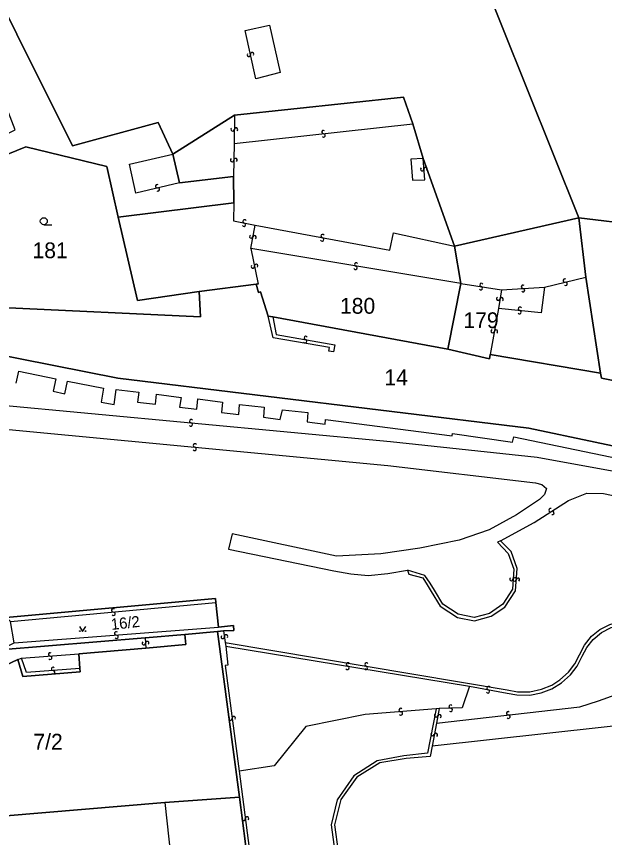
# Model space of a CAD drawing. Extents: x -600309 to -598967, y -1161267 to -1160292.
# Drawn here: x -599203 to -599139.6, y -1160958.3 to -1160869.9 of the extents above; entities that cross this region are included whole.
import ezdxf

# ---------------------------------------------------------------- set-up
doc = ezdxf.new("R2010")
doc.units = 0
for name, color, linetype in [('Level 1', 7, 'Continuous'), ('Level 13', 7, 'Continuous'), ('Level 3', 7, 'Continuous'), ('Level 4', 7, 'Continuous'), ('Level 5', 7, 'Continuous'), ('Level 60', 7, 'Continuous')]:
    doc.layers.add(name, color=color, linetype=linetype)

msp = doc.modelspace()

# ---------------------------------------------------------------- linework, layer by layer
at = {"layer": 'Level 1'}
for points in [[(-599186.14, -1160884.73), (-599187.69, -1160881.34), (-599196.93, -1160883.84), (-599214.95, -1160847.74), (-599222.56, -1160818.46), (-599226.63, -1160790.42), (-599226.46, -1160779.61), (-599224.76, -1160776.46), (-599213.89, -1160771.2), (-599202.26, -1160766.2), (-599191.88, -1160764.74), (-599191.33, -1160772.76), (-599189.43, -1160772.06)], [(-599142.41, -1160891.59), (-599164.5, -1160836.42)], [(-599179.49, -1160880.56), (-599161.27, -1160878.6), (-599160.28, -1160881.49)], [(-599186.14, -1160884.73), (-599179.49, -1160880.56)], [(-599160.28, -1160881.49), (-599159.17, -1160885.23)], [(-599210.91, -1160887.57), (-599201.97, -1160883.95), (-599193.25, -1160886.06), (-599192, -1160891.53)], [(-599185.42, -1160887.84), (-599186.14, -1160884.73)], [(-599159.17, -1160885.23), (-599155.79, -1160894.66)], [(-599179.59, -1160887.16), (-599185.42, -1160887.84)], [(-599179.57, -1160890), (-599179.59, -1160887.16)], [(-599192, -1160891.53), (-599179.57, -1160890)], [(-599183.27, -1160899.54), (-599189.93, -1160900.51), (-599192, -1160891.53)], [(-599155.79, -1160894.66), (-599142.41, -1160891.59)], [(-599135.82, -1160892.38), (-599142.41, -1160891.59)], [(-599141.64, -1160898), (-599142.41, -1160891.59)], [(-599155.1, -1160898.67), (-599155.79, -1160894.66)], [(-599140.05, -1160908.33), (-599141.64, -1160898)], [(-599177.14, -1160898.74), (-599183.27, -1160899.54)], [(-599175.86, -1160902.19), (-599176.67, -1160899.57), (-599176.9, -1160899.65), (-599177.14, -1160898.74)], [(-599156.5, -1160905.76), (-599155.1, -1160898.67)], [(-599183.27, -1160899.54), (-599183.16, -1160902.27), (-599204.59, -1160901.25), (-599205.47, -1160899.62)], [(-599175.37, -1160902.28), (-599175.86, -1160902.19)], [(-599156.5, -1160905.76), (-599175.37, -1160902.28)], [(-599090.81, -1160941.28), (-599095.27, -1160935.88), (-599099.26, -1160932.22), (-599109.1, -1160924.77), (-599133.51, -1160917.28), (-599147.77, -1160914.25), (-599192.06, -1160908.87), (-599213.12, -1160904.7), (-599222.87, -1160911.11), (-599239.81, -1160919.79)], [(-599151.93, -1160906.31), (-599152.02, -1160906.79), (-599156.5, -1160905.76)], [(-599140.05, -1160908.33), (-599151.93, -1160906.31)], [(-599134.1, -1160910.05), (-599139.96, -1160908.88), (-599140.05, -1160908.33)], [(-599204.06, -1160934.65), (-599181.54, -1160932.59), (-599181.49, -1160933.03)], [(-599181.49, -1160933.03), (-599181.2, -1160935.69)], [(-599181.2, -1160935.69), (-599179.58, -1160935.49), (-599179.54, -1160936.05), (-599180.68, -1160936.08)], [(-599204.74, -1160938.11), (-599189.1, -1160936.84)], [(-599189.1, -1160936.84), (-599184.83, -1160936.46)], [(-599189.04, -1160937.95), (-599184.71, -1160937.54), (-599184.83, -1160936.46)], [(-599184.83, -1160936.46), (-599181.3, -1160936.16)], [(-599180.68, -1160936.08), (-599181.3, -1160936.16)], [(-599181.3, -1160936.16), (-599178.93, -1160953.98)], [(-599196.26, -1160938.56), (-599189.04, -1160937.95)], [(-599196.15, -1160940.15), (-599196.26, -1160938.56)], [(-599228.74, -1160948.86), (-599220.85, -1160947.69), (-599202.82, -1160939.17)], [(-599202.82, -1160939.17), (-599202.27, -1160941.01), (-599196.12, -1160940.49), (-599196.15, -1160940.15)], [(-599225.89, -1160957.84), (-599186.97, -1160954.57)], [(-599186.97, -1160954.57), (-599178.93, -1160953.98)], [(-599178.93, -1160953.98), (-599177.98, -1160961.52), (-599177.34, -1160964.13), (-599176.24, -1160966.62), (-599174.52, -1160969.21), (-599172.33, -1160971.47), (-599158.73, -1160982.53), (-599145.9, -1160990.81), (-599145.8, -1160995.78)]]:
    msp.add_lwpolyline(points, dxfattribs=at)
at = {"layer": 'Level 13'}
for centre, start, end in [((-599177.941, -1160874.058), 139.63293, 11.73093), ((-599177.58, -1160873.982), 319.41848, 192.00848), ((-599179.684, -1160882.078), 126.78257, 359.37257), ((-599179.316, -1160882.083), 306.99703, 179.09503), ((-599169.919, -1160882.366), 43.66387, 275.76186), ((-599169.881, -1160882.733), 223.44941, 96.03941), ((-599179.734, -1160885.375), 125.86733, 358.45733), ((-599179.366, -1160885.386), 306.08178, 178.17978), ((-599159.264, -1160886.372), 131.65561, 3.75361), ((-599158.896, -1160886.347), 311.44116, 184.03116), ((-599187.811, -1160888.201), 50.2152, 282.8052), ((-599187.73, -1160888.56), 230.42966, 102.52766), ((-599178.39, -1160891.98), 25.44674, 257.54474), ((-599178.469, -1160892.34), 205.23229, 77.82229), ((-599177.681, -1160893.625), 116.808, 348.906), ((-599177.319, -1160893.695), 296.59354, 169.18354), ((-599169.985, -1160893.559), 26.94631, 259.04431), ((-599170.054, -1160893.921), 206.73186, 79.32186), ((-599177.52, -1160896.857), 139.16057, 11.75057), ((-599177.159, -1160896.783), 319.37503, 191.47303), ((-599166.452, -1160896.982), 207.96788, 80.06587), ((-599166.389, -1160896.619), 27.75342, 260.34342), ((-599152.89, -1160898.828), 28.52808, 260.62607), ((-599148.419, -1160899.026), 40.82605, 272.92405), ((-599143.901, -1160898.36), 50.89281, 282.99081), ((-599143.818, -1160898.719), 230.67836, 103.26836), ((-599152.949, -1160899.192), 208.31362, 80.90362), ((-599148.4, -1160899.394), 220.61159, 93.20159), ((-599151.081, -1160900.319), 117.78889, 350.37889), ((-599150.718, -1160900.382), 298.00335, 170.10134), ((-599148.74, -1160901.407), 31.21398, 263.80398), ((-599148.781, -1160901.773), 211.42843, 83.52643), ((-599151.681, -1160903.797), 117.20962, 349.79962), ((-599151.319, -1160903.864), 297.42407, 169.52207), ((-599171.873, -1160904.901), 207.00533, 79.59533), ((-599171.806, -1160904.539), 27.21978, 259.31778), ((-599184.188, -1160913.863), 211.79089, 84.38089), ((-599184.151, -1160913.497), 32.00535, 264.10335), ((-599183.778, -1160916.483), 211.70559, 84.29559), ((-599183.741, -1160916.117), 31.92005, 264.01805), ((-599145.449, -1160923.074), 70.23301, 302.33101), ((-599145.251, -1160923.385), 250.01855, 122.60855), ((-599149.664, -1160930.516), 123.18578, 355.77578), ((-599149.324, -1160930.545), 123.33781, 355.4358), ((-599149.296, -1160930.544), 303.40024, 175.49823), ((-599148.956, -1160930.574), 303.12335, 175.71335), ((-599192.555, -1160933.876), 42.67233, 274.77033), ((-599192.524, -1160934.243), 222.45788, 95.04788), ((-599192.222, -1160936.356), 41.76149, 273.85949), ((-599192.197, -1160936.724), 221.54703, 94.13703), ((-599180.752, -1160936.73), 136.69491, 9.28491), ((-599180.388, -1160936.671), 316.90937, 189.00737), ((-599189.254, -1160937.409), 130.25234, 2.84234), ((-599188.886, -1160937.392), 310.46679, 182.56479), ((-599199.353, -1160938.616), 41.82114, 273.91914), ((-599199.327, -1160938.984), 221.60669, 94.19669), ((-599167.258, -1160939.708), 28.02376, 260.12175), ((-599165.268, -1160939.698), 27.83081, 259.92881), ((-599199.033, -1160940.176), 41.34319, 273.93319), ((-599199.008, -1160940.544), 221.55765, 93.65565), ((-599167.321, -1160940.071), 207.8093, 80.3993), ((-599165.331, -1160940.061), 207.61635, 80.20635), ((-599152.116, -1160942.239), 27.1303, 259.2283), ((-599152.184, -1160942.601), 206.91584, 79.50584), ((-599161.593, -1160944.606), 41.55698, 274.14698), ((-599161.568, -1160944.974), 221.77144, 93.86944), ((-599156.204, -1160944.236), 38.77507, 271.36507), ((-599156.196, -1160944.604), 218.98952, 91.08752), ((-599150.019, -1160944.957), 43.83501, 275.933), ((-599179.923, -1160945.523), 134.70353, 7.29353), ((-599179.557, -1160945.477), 314.91799, 187.01599), ((-599157.761, -1160945.206), 116.62735, 349.21735), ((-599157.399, -1160945.275), 296.84181, 168.9398), ((-599149.98, -1160945.323), 223.62055, 96.21055), ((-599158.151, -1160947.214), 116.16095, 348.75095), ((-599157.789, -1160947.287), 296.3754, 168.4734), ((-599178.503, -1160956.343), 134.61361, 7.20361), ((-599178.137, -1160956.298), 314.82806, 186.92606)]:
    msp.add_arc(centre, 0.184, start, end, dxfattribs=at)
at = {"layer": 'Level 3'}
for points in [[(-599178.33, -1160871.42), (-599175.71, -1160870.84), (-599174.55, -1160875.95), (-599177.2, -1160876.62), (-599178.33, -1160871.42)], [(-599179.49, -1160880.56), (-599179.51, -1160883.61)], [(-599179.51, -1160883.61), (-599160.28, -1160881.49)], [(-599179.51, -1160883.61), (-599179.59, -1160887.16)], [(-599185.42, -1160887.84), (-599190.12, -1160888.93), (-599190.79, -1160885.84), (-599186.14, -1160884.73)], [(-599159.17, -1160885.23), (-599160.48, -1160885.29), (-599160.32, -1160887.54), (-599159, -1160887.5), (-599159.17, -1160885.23)], [(-599179.57, -1160890), (-599179.59, -1160891.91), (-599177.27, -1160892.4)], [(-599177.74, -1160894.92), (-599177.27, -1160892.4)], [(-599177.27, -1160892.4), (-599162.76, -1160895.07), (-599162.34, -1160893.21), (-599155.79, -1160894.66)], [(-599155.1, -1160898.67), (-599177.74, -1160894.92)], [(-599177.74, -1160894.92), (-599176.93, -1160898.73), (-599177.14, -1160898.74)], [(-599146.09, -1160899.07), (-599141.64, -1160898)], [(-599155.1, -1160898.67), (-599150.73, -1160899.35)], [(-599146.09, -1160899.07), (-599146.45, -1160901.83), (-599151.06, -1160901.35)], [(-599150.73, -1160899.35), (-599151.06, -1160901.35)], [(-599150.73, -1160899.35), (-599146.09, -1160899.07)], [(-599151.06, -1160901.35), (-599151.93, -1160906.31)], [(-599175.37, -1160902.28), (-599174.99, -1160904.15), (-599168.68, -1160905.28), (-599168.83, -1160906.05), (-599169.31, -1160905.97), (-599169.26, -1160905.56), (-599175.3, -1160904.51), (-599175.86, -1160902.19)], [(-599202.98, -1160909.4), (-599202.71, -1160908.12), (-599198.71, -1160908.95), (-599199.01, -1160910.28), (-599197.77, -1160910.55), (-599197.47, -1160909.18), (-599193.58, -1160909.96), (-599193.83, -1160911.46), (-599192.44, -1160911.7), (-599192.21, -1160910.08), (-599189.77, -1160910.37), (-599189.94, -1160911.46), (-599187.98, -1160911.67), (-599187.89, -1160910.61), (-599185.22, -1160910.94), (-599185.4, -1160912.01), (-599183.55, -1160912.2), (-599183.42, -1160911.11), (-599180.76, -1160911.45), (-599180.9, -1160912.58), (-599179.02, -1160912.79), (-599178.95, -1160911.69), (-599176.28, -1160912.01), (-599176.37, -1160913.06), (-599174.56, -1160913.32), (-599174.33, -1160912.29), (-599171.57, -1160912.58), (-599171.65, -1160913.59), (-599169.72, -1160913.81), (-599169.67, -1160913.31), (-599156.04, -1160915.08), (-599156.01, -1160914.83), (-599149.53, -1160915.76), (-599149.41, -1160915.17), (-599134.18, -1160918.35)], [(-599237.16, -1160924.23), (-599217.67, -1160913.88), (-599211.9, -1160912.1), (-599205.67, -1160911.66), (-599162.67, -1160915.7), (-599146.88, -1160917.38), (-599132.9, -1160919.94), (-599119.14, -1160923.19), (-599114.23, -1160925.05), (-599109.69, -1160927.43), (-599105.45, -1160930.09), (-599102.83, -1160932.05), (-599099.44, -1160935.38), (-599096.48, -1160939.5), (-599095.29, -1160943.46), (-599096.44, -1160948), (-599103.45, -1160958.99), (-599112.91, -1160969.26)], [(-599236.27, -1160926.87), (-599217.62, -1160916.69), (-599211.29, -1160914.58), (-599204.55, -1160914.31), (-599162.96, -1160918.28), (-599147.06, -1160920.15), (-599146.37, -1160920.32), (-599145.88, -1160920.74), (-599146.11, -1160921.4), (-599146.64, -1160921.92), (-599149.11, -1160923.59), (-599152.05, -1160925.2), (-599155.27, -1160926.31), (-599159.53, -1160927.18), (-599163.73, -1160927.77), (-599168.48, -1160928.03), (-599179.74, -1160925.62), (-599180.14, -1160927.28), (-599168.8, -1160929.61), (-599166.95, -1160929.93), (-599165.1, -1160930.12), (-599162.97, -1160929.91), (-599160.84, -1160929.55)], [(-599150.84, -1160926.37), (-599147.2, -1160924.43), (-599143.5, -1160922.04), (-599141.53, -1160921.24), (-599139.75, -1160921.28), (-599136.47, -1160921.97)], [(-599150.84, -1160926.37), (-599151.14, -1160926.53), (-599150, -1160927.74), (-599149.4, -1160929.45), (-599149.55, -1160931.61), (-599150.58, -1160933.21), (-599152.02, -1160934.21), (-599153.68, -1160934.63), (-599155.4, -1160934.28), (-599157.04, -1160933.2), (-599157.95, -1160931.7), (-599158.41, -1160930.94), (-599158.98, -1160930.12), (-599160.84, -1160929.55)], [(-599160.84, -1160929.55), (-599160.72, -1160929.96), (-599159.19, -1160930.38), (-599158.74, -1160931.12), (-599158.31, -1160931.86), (-599157.32, -1160933.44), (-599155.47, -1160934.65), (-599153.63, -1160935.01), (-599151.83, -1160934.49), (-599150.35, -1160933.52), (-599149.22, -1160931.77), (-599149.05, -1160929.36), (-599149.69, -1160927.53), (-599150.84, -1160926.37)], [(-599203.59, -1160935.08), (-599181.49, -1160933.03)], [(-599180.47, -1160937.33), (-599150.13, -1160942.43), (-599148.99, -1160942.65), (-599147.68, -1160942.65), (-599146.41, -1160942.38), (-599145.31, -1160941.93), (-599144.44, -1160941.37), (-599143.52, -1160940.53), (-599142.83, -1160939.62), (-599142.32, -1160938.66), (-599141.8, -1160937.62), (-599141.03, -1160936.66), (-599140.13, -1160935.93), (-599139.07, -1160935.39), (-599137.87, -1160935.04), (-599136.58, -1160934.98)], [(-599203.22, -1160937.38), (-599181.2, -1160935.69)], [(-599154.17, -1160942.05), (-599150.13, -1160942.78), (-599149.06, -1160942.99), (-599147.67, -1160943.01), (-599146.46, -1160942.77), (-599145.32, -1160942.33), (-599144.25, -1160941.69), (-599143.3, -1160940.82), (-599142.58, -1160939.88), (-599142.02, -1160938.81), (-599141.54, -1160937.89), (-599140.84, -1160937), (-599139.94, -1160936.26), (-599138.93, -1160935.73), (-599137.7, -1160935.41), (-599136.58, -1160935.36)], [(-599189.1, -1160936.84), (-599189.04, -1160937.95)], [(-599180.68, -1160936.08), (-599180.47, -1160937.33)], [(-599180.41, -1160937.73), (-599180.2, -1160939.77), (-599180.5, -1160939.8), (-599178.99, -1160951.2)], [(-599180.47, -1160937.33), (-599180.41, -1160937.73)], [(-599180.41, -1160937.73), (-599154.17, -1160942.05)], [(-599202.43, -1160939.04), (-599196.26, -1160938.56)], [(-599157.73, -1160946.02), (-599142.28, -1160944.27), (-599140.29, -1160943.63), (-599138.37, -1160942.94), (-599137.4, -1160942.21), (-599136.78, -1160940.53), (-599136.47, -1160938.59)], [(-599202.82, -1160939.17), (-599202.43, -1160939.04)], [(-599196.15, -1160940.15), (-599201.89, -1160940.57), (-599202.43, -1160939.04)], [(-599154.17, -1160942.05), (-599154.96, -1160944.39), (-599157.44, -1160944.46)], [(-599157.75, -1160944.49), (-599165.42, -1160945.08), (-599171.8, -1160946.39), (-599175.2, -1160950.63), (-599178.99, -1160951.2)], [(-599157.75, -1160944.49), (-599158.69, -1160949.24), (-599161.23, -1160949.53), (-599164.13, -1160950.09), (-599166.62, -1160951.69), (-599168.44, -1160954.29), (-599169.07, -1160956.96), (-599168.68, -1160959.89), (-599166.9, -1160962.85), (-599169.94, -1160967.32), (-599173.79, -1160965.72), (-599175.85, -1160966.56)], [(-599167.37, -1160964.08), (-599145.71, -1160979.34), (-599143.04, -1160980.89), (-599139.54, -1160981.78), (-599136.05, -1160981.78), (-599132.77, -1160981.34), (-599129.15, -1160979.87), (-599126.44, -1160978.08), (-599119.63, -1160972.32), (-599112.51, -1160965.29), (-599105.65, -1160957.58), (-599100.74, -1160950.13), (-599100.79, -1160948.38), (-599101.42, -1160946.69), (-599102.51, -1160945.5), (-599103.95, -1160944.85), (-599105.64, -1160944.69), (-599120.09, -1160944.82), (-599133.48, -1160945.79), (-599158.21, -1160948.49)], [(-599157.44, -1160944.46), (-599157.75, -1160944.49)], [(-599157.44, -1160944.46), (-599157.73, -1160946.02)], [(-599157.73, -1160946.02), (-599158.21, -1160948.49)], [(-599158.21, -1160948.49), (-599158.42, -1160949.61), (-599160.98, -1160949.83), (-599163.83, -1160950.31), (-599166.3, -1160951.83), (-599168.04, -1160954.23), (-599168.72, -1160956.97), (-599168.32, -1160959.84), (-599166.49, -1160962.75), (-599167.37, -1160964.08)], [(-599178.99, -1160951.2), (-599177.65, -1160961.44), (-599177.01, -1160964.12), (-599175.85, -1160966.56)], [(-599186.97, -1160954.57), (-599185.91, -1160964.43)]]:
    msp.add_lwpolyline(points, dxfattribs=at)
at = {"layer": 'Level 5'}
msp.add_line((-599200.02, -1160892.34), (-599199.145, -1160892.34), dxfattribs=at)
msp.add_lwpolyline([(-599196.181, -1160935.63), (-599195.84, -1160936.14), (-599195.5, -1160935.63)], dxfattribs=at)
for centre, radius in [((-599200.02, -1160891.965), 0.375), ((-599196.146, -1160936.106), 0.034), ((-599195.535, -1160936.106), 0.034)]:
    msp.add_circle(centre, radius, dxfattribs=at)
at = {"layer": 'Level 60'}
for points in [[(-599189.43, -1160772.06), (-599179.89, -1160797.48), (-599173.47, -1160813.83), (-599164.5, -1160836.42), (-599142.41, -1160891.59), (-599155.79, -1160894.66), (-599159.17, -1160885.23), (-599160.28, -1160881.49), (-599161.27, -1160878.6), (-599179.49, -1160880.56), (-599186.14, -1160884.73), (-599187.69, -1160881.34), (-599196.93, -1160883.84), (-599214.95, -1160847.74), (-599222.56, -1160818.46), (-599226.63, -1160790.42), (-599226.46, -1160779.61), (-599224.76, -1160776.46), (-599213.89, -1160771.2), (-599202.26, -1160766.2), (-599191.88, -1160764.74), (-599191.33, -1160772.76)], [(-599148.07, -1160834.06), (-599144.32, -1160833.5), (-599143.7, -1160838.22), (-599142.53, -1160847.08), (-599139.73, -1160846.68), (-599139.53, -1160848.36), (-599138.49, -1160848.22), (-599138.25, -1160849.52), (-599137.1, -1160849.29), (-599128.85, -1160882.9), (-599125.17, -1160882.5), (-599123.68, -1160893.79), (-599128.8, -1160893.18), (-599135.82, -1160892.38), (-599142.41, -1160891.59), (-599164.5, -1160836.42), (-599173.47, -1160813.83), (-599166.28, -1160811.87), (-599162.9, -1160818.7), (-599160.58, -1160821.87), (-599156.32, -1160823.81), (-599149.81, -1160823.62), (-599148.3, -1160834.08)], [(-599155.1, -1160898.67), (-599156.5, -1160905.76), (-599175.37, -1160902.28), (-599175.86, -1160902.19), (-599176.67, -1160899.57), (-599176.9, -1160899.65), (-599177.14, -1160898.74), (-599183.27, -1160899.54), (-599189.93, -1160900.51), (-599192, -1160891.53), (-599179.57, -1160890), (-599179.59, -1160887.16), (-599185.42, -1160887.84), (-599186.14, -1160884.73), (-599179.49, -1160880.56), (-599161.27, -1160878.6), (-599160.28, -1160881.49), (-599159.17, -1160885.23), (-599155.79, -1160894.66)], [(-599189.93, -1160900.51), (-599183.27, -1160899.54), (-599183.16, -1160902.27), (-599204.59, -1160901.25), (-599205.47, -1160899.62), (-599210.91, -1160887.57), (-599201.97, -1160883.95), (-599193.25, -1160886.06), (-599192, -1160891.53)], [(-599141.64, -1160898), (-599140.05, -1160908.33), (-599151.93, -1160906.31), (-599152.02, -1160906.79), (-599156.5, -1160905.76), (-599155.1, -1160898.67), (-599155.79, -1160894.66), (-599142.41, -1160891.59)], [(-599142.41, -1160891.59), (-599135.82, -1160892.38), (-599135.58, -1160894.37), (-599134.99, -1160900.44), (-599134.1, -1160910.05), (-599139.96, -1160908.88), (-599140.05, -1160908.33), (-599141.64, -1160898)], [(-599189.1, -1160936.84), (-599204.74, -1160938.11), (-599203.22, -1160937.38), (-599203.59, -1160935.08), (-599204.06, -1160934.65), (-599181.54, -1160932.59), (-599181.49, -1160933.03), (-599181.2, -1160935.69), (-599179.58, -1160935.49), (-599179.54, -1160936.05), (-599180.68, -1160936.08), (-599181.3, -1160936.16), (-599184.83, -1160936.46)], [(-599229.19, -1160947.31), (-599221.58, -1160946.14), (-599204.74, -1160938.11), (-599189.1, -1160936.84), (-599184.83, -1160936.46), (-599184.71, -1160937.54), (-599189.04, -1160937.95), (-599196.26, -1160938.56), (-599196.15, -1160940.15), (-599196.12, -1160940.49), (-599202.27, -1160941.01), (-599202.82, -1160939.17), (-599220.85, -1160947.69), (-599228.74, -1160948.86)]]:
    msp.add_lwpolyline(points, close=True, dxfattribs=at)
for points in [[(-599226.46, -1160779.61), (-599226.63, -1160790.42), (-599222.56, -1160818.46), (-599214.95, -1160847.74), (-599196.93, -1160883.84), (-599187.69, -1160881.34), (-599186.14, -1160884.73), (-599185.42, -1160887.84), (-599179.59, -1160887.16), (-599179.57, -1160890), (-599192, -1160891.53), (-599193.25, -1160886.06), (-599201.97, -1160883.95), (-599210.91, -1160887.57), (-599214.32, -1160887.67), (-599203.12, -1160882.13), (-599222.91, -1160830.72), (-599230, -1160803.14), (-599278.59, -1160851.16), (-599296.81, -1160821.25), (-599308.94, -1160799.38)], [(-599204.59, -1160901.25), (-599183.16, -1160902.27), (-599183.27, -1160899.54), (-599177.14, -1160898.74), (-599176.9, -1160899.65), (-599176.67, -1160899.57), (-599175.86, -1160902.19), (-599175.37, -1160902.28), (-599156.5, -1160905.76), (-599152.02, -1160906.79), (-599151.93, -1160906.31), (-599140.05, -1160908.33), (-599139.96, -1160908.88), (-599134.1, -1160910.05)], [(-599133.51, -1160917.28), (-599147.77, -1160914.25), (-599192.06, -1160908.87), (-599213.12, -1160904.7)], [(-599213.12, -1160904.7), (-599192.06, -1160908.87), (-599147.77, -1160914.25), (-599133.51, -1160917.28), (-599109.1, -1160924.77), (-599099.26, -1160932.22), (-599095.27, -1160935.88), (-599090.81, -1160941.28), (-599097.65, -1160994.22)], [(-599177.98, -1160961.52), (-599178.93, -1160953.98), (-599181.3, -1160936.16), (-599180.68, -1160936.08), (-599179.54, -1160936.05), (-599179.58, -1160935.49), (-599181.2, -1160935.69), (-599181.49, -1160933.03), (-599181.54, -1160932.59), (-599204.06, -1160934.65)], [(-599220.85, -1160947.69), (-599202.82, -1160939.17), (-599202.27, -1160941.01), (-599196.12, -1160940.49), (-599196.15, -1160940.15), (-599196.26, -1160938.56), (-599189.04, -1160937.95), (-599184.71, -1160937.54), (-599184.83, -1160936.46), (-599181.3, -1160936.16), (-599178.93, -1160953.98), (-599186.97, -1160954.57), (-599225.89, -1160957.84)], [(-599254.15, -1160960.71), (-599237.54, -1160951.25), (-599236.39, -1160950.59), (-599236.71, -1160949.88), (-599234.65, -1160948.91), (-599234.2, -1160950.29), (-599233.11, -1160949.85), (-599230.35, -1160958.24), (-599226.78, -1160957.92), (-599225.89, -1160957.84), (-599186.97, -1160954.57), (-599178.93, -1160953.98), (-599177.98, -1160961.52)]]:
    msp.add_lwpolyline(points, dxfattribs=at)

# ---------------------------------------------------------------- texts
at = {"layer": 'Level 4'}
for s, p in [('181', (-599201.24, -1160895.95)), ('180', (-599168.12, -1160901.93)), ('179', (-599154.832, -1160903.48)), ('14', (-599163.34, -1160909.63)), ('7/2', (-599201.142, -1160948.87))]:
    msp.add_text(s, height=1.7, dxfattribs=at).set_placement(p)
msp.add_text('16/2', height=1.2, rotation=6.3, dxfattribs=at).set_placement((-599192.73, -1160935.99))

doc.saveas('drawing.dxf')
